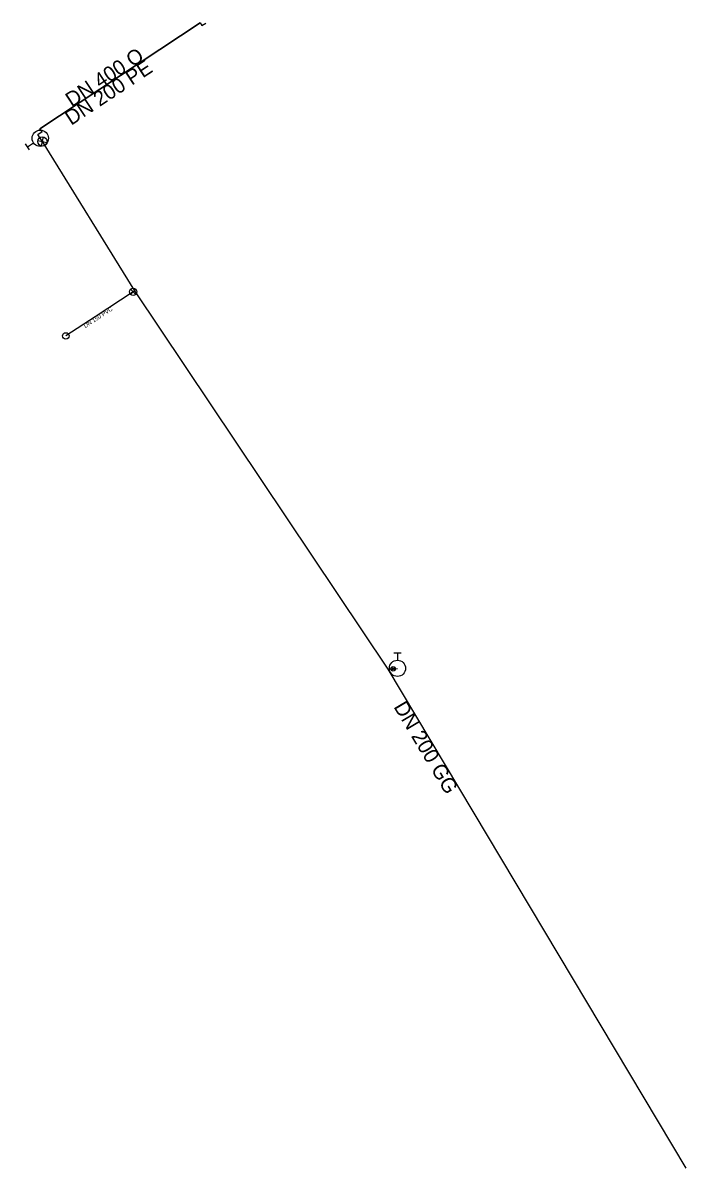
# Model space of a CAD drawing. Extents: x -451501 to -451094, y -1102108 to -1101623.
# Drawn here: x -451165.9 to -451094.1, y -1101907.6 to -1101783.5 of the extents above; entities that cross this region are included whole.
import ezdxf

# ---------------------------------------------------------------- set-up
doc = ezdxf.new("R2010")
doc.units = 0
for name, color, linetype in [('_hydrantova_odbocka_', 7, 'Continuous'), ('_pripojka_priblizne_', 7, 'Continuous'), ('_voda_smvak_prevzato_z_dokumentace_', 7, 'Continuous'), ('_voda_smvak_priblizne_', 7, 'Continuous'), ('_vodovodni_chranicka_', 7, 'Continuous'), ('Default', 7, 'Continuous'), ('MoLevel 2', 7, 'Continuous'), ('MoLevel 27', 7, 'Continuous'), ('MoLevel 28', 7, 'Continuous'), ('MoLevel 30', 7, 'Continuous'), ('MoLevel 32', 7, 'Continuous'), ('MoLevel 46', 7, 'Continuous'), ('MoLevel 53', 7, 'Continuous'), ('MoLevel 60', 7, 'Continuous')]:
    doc.layers.add(name, color=color, linetype=linetype)

# ---------------------------------------------------------------- blocks, each defined once
blk = doc.blocks.new('_uzaver_')
at = {"layer": 'Default'}
for p, q in [((-0.000035, -0.000035), (0.000035, 0.000035)), ((0.000035, -0.000035), (-0.000035, 0.000035))]:
    blk.add_line(p, q, dxfattribs=at)
for radius in [0.00005, 0.0000025]:
    blk.add_circle((0, 0), radius, dxfattribs=at)
blk = doc.blocks.new('_uzaver_pripojka_')
at = {"layer": 'Default'}
for p, q in [((-0.000035, -0.000035), (0.000035, 0.000035)), ((0.000035, -0.000035), (-0.000035, 0.000035))]:
    blk.add_line(p, q, dxfattribs=at)
for radius in [0.00005, 0.0000025]:
    blk.add_circle((0, 0), radius, dxfattribs=at)
blk = doc.blocks.new('_hydrant_voda_')
at = {"layer": 'Default'}
for p, q in [((-0.0000225, 0.000095), (0.0000225, 0.000095)), ((0, 0.000095), (0, 0.00005))]:
    blk.add_line(p, q, dxfattribs=at)
blk.add_circle((0, 0), 0.00005, dxfattribs=at)
blk = doc.blocks.new('_sachta_voda_')
at = {"layer": 'Default'}
blk.add_circle((0, 0), 0.000035, dxfattribs=at)

msp = doc.modelspace()

# ---------------------------------------------------------------- linework, layer by layer
at = {"layer": '_hydrantova_odbocka_'}
for p, q in [((-451126.34, -1101853.56), (-451125.8, -1101853.52)), ((-451125.8, -1101853.52), (-451125.33, -1101853.47))]:
    msp.add_line(p, q, dxfattribs=at)
at = {"layer": '_pripojka_priblizne_'}
msp.add_line((-451158.1, -1101815.37), (-451161.26, -1101817.44), dxfattribs=at)
msp.add_lwpolyline([(-451153.78, -1101812.57), (-451153.97, -1101812.66), (-451158.1, -1101815.37)], dxfattribs=at)
at = {"layer": '_voda_smvak_prevzato_z_dokumentace_'}
msp.add_lwpolyline([(-451094.06, -1101907.63), (-451126.34, -1101853.56), (-451153.78, -1101812.57), (-451163.8, -1101796.36), (-451163.8, -1101796.36)], dxfattribs=at)
at = {"layer": '_voda_smvak_priblizne_'}
for p, q in [((-451164.03, -1101796.02), (-451164.3, -1101795.62)), ((-451163.8, -1101796.36), (-451164.03, -1101796.02))]:
    msp.add_line(p, q, dxfattribs=at)
msp.add_lwpolyline([(-451164.3, -1101795.62), (-451163.84, -1101795.3), (-451164.06, -1101794.98), (-451146.72, -1101783.51), (-451146.51, -1101783.81), (-451146.1, -1101783.54)], dxfattribs=at)
at = {"layer": '_vodovodni_chranicka_'}
msp.add_line((-451146.72, -1101783.51), (-451164.06, -1101794.98), dxfattribs=at)

# ---------------------------------------------------------------- block references
at = {"layer": 'MoLevel 27', "xscale": 10000.000000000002, "yscale": 10000, "rotation": -58.282993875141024}
msp.add_blockref('_uzaver_', (-451163.8, -1101796.36), dxfattribs=at)
at = {"layer": 'MoLevel 27', "xscale": 5000, "yscale": 5000}
msp.add_blockref('_uzaver_', (-451125.8, -1101853.52), dxfattribs=at)
at = {"layer": 'MoLevel 28', "xscale": 17636.68430335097, "yscale": 17636.684303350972, "rotation": 124.03604710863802}
msp.add_blockref('_hydrant_voda_', (-451164.03, -1101796.02), dxfattribs=at)
at = {"layer": 'MoLevel 28', "xscale": 17636.68430335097, "yscale": 17636.68430335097}
msp.add_blockref('_hydrant_voda_', (-451125.33, -1101853.47), dxfattribs=at)
at = {"layer": 'MoLevel 30', "xscale": 10000, "yscale": 10000}
msp.add_blockref('_sachta_voda_', (-451161.26, -1101817.44), dxfattribs=at)
at = {"layer": 'MoLevel 53', "xscale": 7999.999999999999, "yscale": 7999.999999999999}
msp.add_blockref('_uzaver_pripojka_', (-451153.97, -1101812.66), dxfattribs=at)

# ---------------------------------------------------------------- texts
at = {"layer": 'MoLevel 2'}
msp.add_text('DN 200 PE', height=1.605, rotation=33.4858, dxfattribs=at).set_placement((-451160.68, -1101794.67))
at = {"layer": 'MoLevel 32'}
msp.add_text('DN 150 PVC', height=0.455, rotation=33.2519, dxfattribs=at).set_placement((-451159.15, -1101816.6))
at = {"layer": 'MoLevel 46'}
msp.add_text('DN 200 GG', height=1.605, rotation=300.8349, dxfattribs=at).set_placement((-451125.79, -1101857.63))
at = {"layer": 'MoLevel 60'}
msp.add_text('DN 400 O', height=1.605, rotation=33.4858, dxfattribs=at).set_placement((-451160.62, -1101792.7))

doc.saveas('drawing.dxf')
